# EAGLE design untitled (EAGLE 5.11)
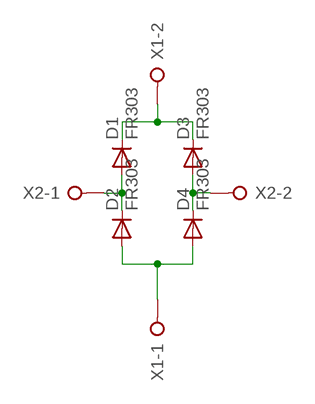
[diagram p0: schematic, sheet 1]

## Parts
D1  FR303  1N5400  [DO201-15]
D2  FR303  1N5400  [DO201-15]
D3  FR303  1N5400  [DO201-15]
D4  FR303  1N5400  [DO201-15]
X1  W237-02P  [W237-132]
X2  W237-02P  [W237-132]

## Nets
N$1: D1.A D2.C X2.1
N$2: D3.A D4.C X2.2
N$3: D2.A D4.A X1.1
N$4: D1.C D3.C X1.2

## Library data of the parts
D1-D4 = diode:1N5400: DIODE
X1 X2 = con-wago-508:W237-02P: WAGO SREW CLAMP; OC_FARNELL: unknown; OC_NEWARK: unknown

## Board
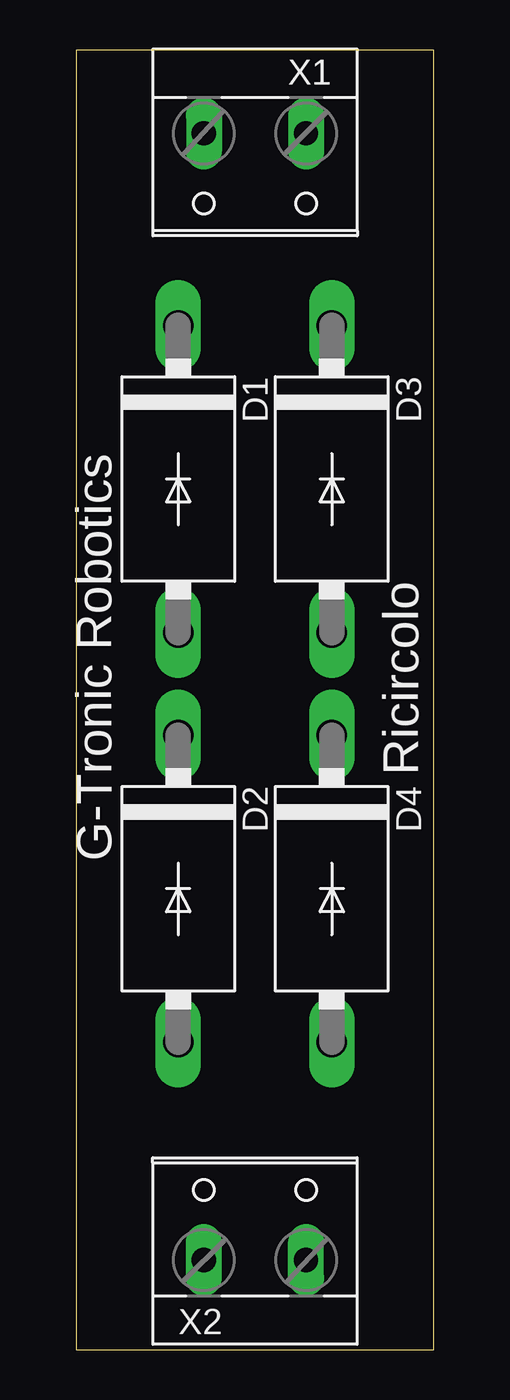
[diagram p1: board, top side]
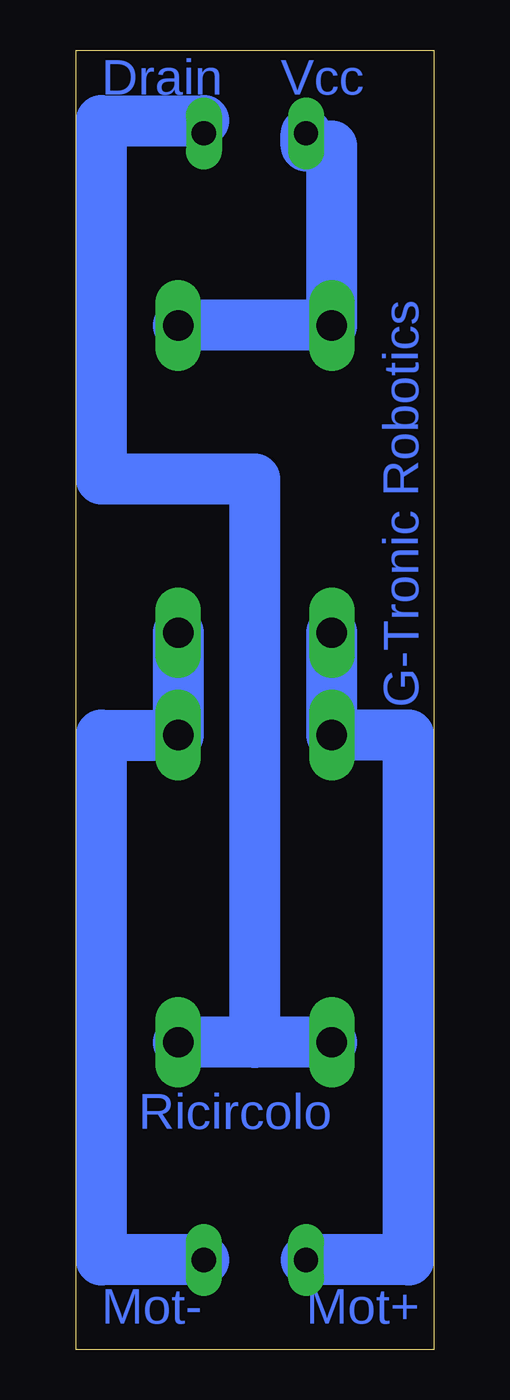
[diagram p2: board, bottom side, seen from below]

Size 17.76 x 64.44 mm. Coordinates in mm from the lower left corner, seen from the top.
Outline: 0,0 17.76,0 17.76,64.44 0,64.44 0,0
Copper layers (1*16): Top 0.035mm / dielectric 1.5mm / Bottom 0.035mm
Design rules "default": minimum track width 10mil, minimum drill 24mil, track to track 8mil, track to pad 8mil, pad to pad 8mil, via to via 8mil, smd to smd 8mil, copper to edge 40mil, drill to drill 8mil, minimum pad ring 10mil, minimum via ring 8mil, stop-mask expansion 4mil, vias tented up to drill 0mil, thermal gap 10mil

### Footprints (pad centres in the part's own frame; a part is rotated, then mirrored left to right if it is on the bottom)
DO201-15 = drill 1.499 long: A 7.62,0; C -7.62,0
W237-132 = drill 1.194 long: 1 -2.54,-0.635; 2 2.54,-0.635

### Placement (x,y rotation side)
D1  5.08,43.18 270 top
D2  5.08,22.86 270 top
D3  12.7,43.18 270 top
D4  12.7,22.86 270 top
X1  8.89,59.69 180 top
X2  8.89,5.08 0 top

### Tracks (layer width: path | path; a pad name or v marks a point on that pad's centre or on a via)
N$1
  Bottom 2.54: X2.1 1.27,4.45 1.27,30.48 D2.C D1.A
N$2
  Bottom 2.54: X2.2 16.51,4.45 16.51,30.48 D4.C D3.A
N$3
  Bottom 0.406: D2.A 8.89,15.24 | 11.43,60.96 X1.1
  Bottom 2.54: D2.A D4.A | 8.89,15.24 8.89,43.18 16.51,43.18 16.51,60.96 11.43,60.96
N$4
  Bottom 0.406: 5.08,59.69 6.35,59.69
  Bottom 2.54: D3.C D1.C 5.08,59.69 | 6.35,59.69 X1.2

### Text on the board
Bottom: Vcc | Drain | G-Tronic Robotics | Ricircolo | Mot+ | Mot-
tNames: G-Tronic Robotics | Ricircolo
